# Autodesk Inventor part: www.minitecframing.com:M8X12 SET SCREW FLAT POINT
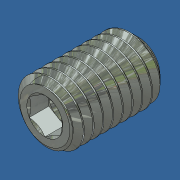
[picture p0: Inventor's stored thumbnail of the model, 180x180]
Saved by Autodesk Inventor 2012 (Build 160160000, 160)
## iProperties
Created: 2015-06
Material: Steel
Document SubType Name: Modeling
Designer: Admin
Density: 7.85 g/cm^3
Mass: 3.44939 g
Surface Area: 5.54882 cm^2
Volume: 0.439412 cm^3
Description: M8x12 Zinc Plated Set Screw Flat
Translation Standard: STEP AP203
FileName: 93245A142.step
PreProcessor: SolidWorks 2010
PostProcessor: Build: 160, Release: 2012 RTM - Date: Tue 03/01/2011
Sent Units: inch
Uncertainty: 1e-05
Author: Admin
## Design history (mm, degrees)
node "93245A1421"
node "Cut-Extrude12"
node "Base1"
